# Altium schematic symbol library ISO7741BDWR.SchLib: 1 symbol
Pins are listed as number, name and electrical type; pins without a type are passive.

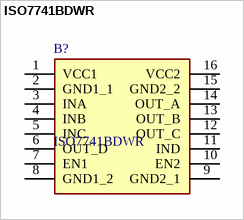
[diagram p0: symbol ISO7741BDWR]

## ISO7741BDWR
designator B?
Digital Isolators Robust EMC, quad-channel, 3/1, reinforced digital isolator 16-SOIC -55 to 125; Manufacturer_Name: Texas Instruments; Geometry.Height: 2.65mm
footprint SOIC127P1030X265-16N
pins: 1 VCC1, 2 GND1_1, 3 INA, 4 INB, 5 INC, 6 OUT_D, 7 EN1, 8 GND1_2, 9 GND2_1, 10 EN2, 11 IND, 12 OUT_C, 13 OUT_B, 14 OUT_A, 15 GND2_2, 16 VCC2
